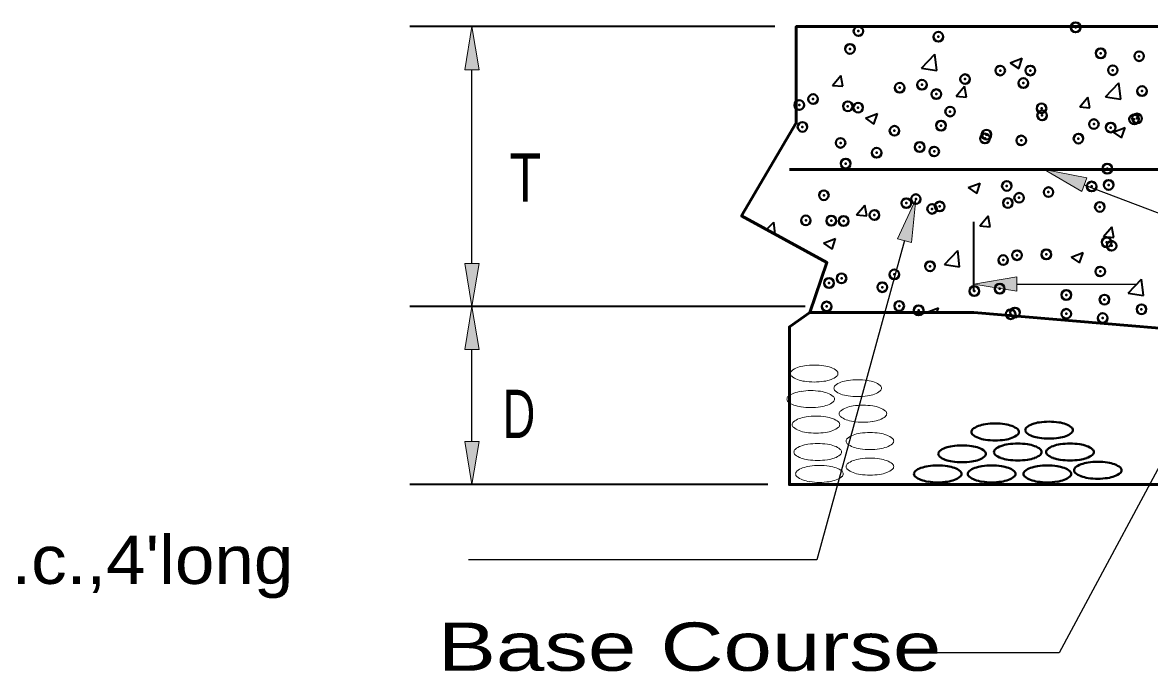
# Model space of a CAD drawing. Extents: x 36.4 to 71.7, y 0.5 to 22.5.
# Drawn here: x 41.345 to 44.615, y 8.235 to 10.118 of the extents above; entities that cross this region are included whole.
import ezdxf

# ---------------------------------------------------------------- set-up
doc = ezdxf.new("R2010")
doc.units = 0
doc.header["$LTSCALE"] = 0.056
doc.header["$PDMODE"] = 32
doc.header["$PDSIZE"] = 0.028
for name, color, linetype, lineweight in [('1', 7, 'Continuous', 40), ('3', 7, 'Continuous', 13), ('6', 7, 'Continuous', 13)]:
    doc.layers.add(name, color=color, linetype=linetype, lineweight=lineweight)

msp = doc.modelspace()

# ---------------------------------------------------------------- hatches: boundary and pattern name
at = {"layer": '1'}
for points in [[(42.67008, 9.98108), (42.62842, 9.98108), (42.64925, 10.10608), (42.64925, 10.10608)], [(42.67008, 9.41925), (42.62842, 9.41925), (42.64925, 9.29425), (42.64925, 9.29425)], [(44.23025, 9.3385), (44.23025, 9.38017), (44.10525, 9.35925), (44.10525, 9.35925)], [(42.67008, 9.16925), (42.62842, 9.16925), (42.64925, 9.29425), (42.64925, 9.29425)], [(42.67008, 8.9025), (42.62842, 8.9025), (42.64925, 8.7775), (42.64925, 8.7775)]]:
    msp.add_hatch(color=256, dxfattribs=at).paths.add_polyline_path(points)
at = {"layer": '3'}
for points in [[(44.41858, 9.62808), (44.43333, 9.667), (44.30908, 9.69192), (44.30908, 9.69192)], [(43.884, 9.49067), (43.92417, 9.47958), (43.93717, 9.60558), (43.93717, 9.60558)]]:
    msp.add_hatch(color=256, dxfattribs=at).paths.add_polyline_path(points)

# ---------------------------------------------------------------- linework, layer by layer
at = {"layer": '1', "lineweight": 35}
for p, q in [((43.52767, 10.10608), (42.46925, 10.10608)), ((43.95358, 9.98558), (43.9925, 10.02617)), ((43.99808, 9.97867), (43.99258, 10.02617)), ((44.21083, 10.0015), (44.24583, 10.015)), ((44.23567, 9.98475), (44.24583, 10.01492)), ((43.95358, 9.98558), (43.99808, 9.97867)), ((44.21083, 10.0015), (44.23567, 9.98475)), ((43.69533, 9.93575), (43.71942, 9.9645)), ((43.72525, 9.93317), (43.71942, 9.9645)), ((44.48725, 9.90283), (44.52617, 9.94342)), ((44.53167, 9.89592), (44.52617, 9.94342)), ((43.69533, 9.93575), (43.72517, 9.93317)), ((44.05392, 9.90442), (44.07808, 9.93308)), ((44.08383, 9.90175), (44.07808, 9.93308)), ((44.05392, 9.90442), (44.08383, 9.90175)), ((44.41258, 9.873), (44.43667, 9.90175)), ((44.4425, 9.87042), (44.43667, 9.90175)), ((44.48725, 9.90283), (44.53167, 9.89592)), ((43.79067, 9.84025), (43.82567, 9.85367)), ((43.81558, 9.8235), (43.82575, 9.85367)), ((44.41258, 9.873), (44.4425, 9.87042)), ((43.79067, 9.84025), (43.81558, 9.8235)), ((44.50925, 9.80025), (44.54425, 9.81367)), ((44.53417, 9.78342), (44.54425, 9.81367)), ((44.50925, 9.80025), (44.53417, 9.78342)), ((44.08917, 9.63892), (44.12417, 9.65242)), ((44.114, 9.62217), (44.12417, 9.65242)), ((44.08917, 9.63892), (44.114, 9.62217)), ((43.76467, 9.55967), (43.78883, 9.58842)), ((43.79458, 9.55708), (43.78883, 9.58842)), ((43.76467, 9.55967), (43.79458, 9.55708)), ((44.12333, 9.52825), (44.14742, 9.557)), ((44.15325, 9.52567), (44.14742, 9.557)), ((43.50425, 9.51725), (43.52525, 9.53917)), ((43.52933, 9.50358), (43.52525, 9.53908)), ((44.10525, 9.33875), (44.10525, 9.53933)), ((44.12333, 9.52825), (44.15325, 9.52567)), ((44.48192, 9.49692), (44.50608, 9.52567)), ((44.51183, 9.49425), (44.50608, 9.52567)), ((43.669, 9.47767), (43.70408, 9.49108)), ((43.69392, 9.46092), (43.70408, 9.49108)), ((44.48192, 9.49692), (44.51183, 9.49433)), ((43.669, 9.47767), (43.69392, 9.46092)), ((44.01992, 9.41575), (44.05883, 9.45633)), ((44.06433, 9.40892), (44.05883, 9.45633)), ((44.38758, 9.43767), (44.42258, 9.45108)), ((44.4125, 9.42083), (44.42258, 9.45108)), ((44.38758, 9.43767), (44.4125, 9.42083)), ((44.01992, 9.41575), (44.06433, 9.40892)), ((44.5535, 9.333), (44.59242, 9.37358)), ((44.598, 9.32608), (44.59242, 9.37358)), ((44.5535, 9.333), (44.598, 9.32608)), ((43.61583, 9.29425), (42.46925, 9.29425)), ((43.9675, 9.27633), (44.0025, 9.28983)), ((43.998, 9.27633), (44.0025, 9.28983)), ((43.9675, 9.27633), (43.96758, 9.27633)), ((43.50792, 8.7775), (42.46925, 8.7775))]:
    msp.add_line(p, q, dxfattribs=at)
at = {"layer": '1', "lineweight": 25}
for p, q in [((42.64925, 9.41925), (42.64925, 9.98108)), ((44.23025, 9.35933), (44.57725, 9.35933)), ((42.64925, 8.9025), (42.64925, 9.16925))]:
    msp.add_line(p, q, dxfattribs=at)
at = {"layer": '1', "lineweight": 53}
msp.add_line((47.36392, 9.69192), (43.57042, 9.69192), dxfattribs=at)
at = {"layer": '1', "lineweight": 13}
msp.add_line((43.61583, 9.29425), (42.46925, 9.29425), dxfattribs=at)
for points in [[(42.67008, 9.98108), (42.62842, 9.98108), (42.64925, 10.10608), (42.64925, 10.10608)], [(42.67008, 9.41925), (42.62842, 9.41925), (42.64925, 9.29425), (42.64925, 9.29425)], [(44.23025, 9.3385), (44.23025, 9.38017), (44.10525, 9.35925), (44.10525, 9.35925)], [(42.67008, 9.16925), (42.62842, 9.16925), (42.64925, 9.29425), (42.64925, 9.29425)], [(42.67008, 8.9025), (42.62842, 8.9025), (42.64925, 8.7775), (42.64925, 8.7775)]]:
    msp.add_lwpolyline(points, close=True, dxfattribs=at)
at = {"layer": '1', "lineweight": 53}
for points in [[(47.51525, 10.10608), (43.59017, 10.10608), (43.59017, 9.827), (43.43175, 9.55683), (43.67933, 9.42175), (43.62983, 9.27633), (44.10525, 9.27633), (46.07633, 9.11), (53.64175, 9.12625)], [(43.62983, 9.27633), (43.57042, 9.23475), (43.57042, 8.7775), (45.24308, 8.7775)]]:
    msp.add_lwpolyline(points, dxfattribs=at)
at = {"layer": '1', "lineweight": 13}
for centre, radius, start, end in [((43.64183, 8.93117), 0.193, 89.84207, 98.25709), ((43.64283, 8.93175), 0.19243, 81.73096, 90.14599), ((43.58358, 9.09958), 0.01025, 180.19847, 229.42992), ((43.5835, 9.0995), 0.01016, 130.3333, 179.56474), ((43.61117, 9.13175), 0.05258, 229.32889, 250.44364), ((43.61142, 9.06742), 0.05269, 109.77026, 130.885), ((43.63008, 9.01542), 0.10795, 98.52638, 109.76521), ((43.6545, 9.015), 0.10836, 70.28977, 81.5286), ((43.67325, 9.06742), 0.05269, 49.11499, 70.22974), ((43.6735, 9.13175), 0.05258, 289.55636, 310.6711), ((43.70117, 9.09958), 0.01012, 359.922, 49.15345), ((43.70108, 9.0995), 0.01021, 311.07972, 0.31117), ((43.63008, 9.18375), 0.10795, 250.23479, 261.47362), ((43.64233, 9.268), 0.19304, 261.57477, 269.98979), ((43.64225, 9.26742), 0.19248, 270.02264, 278.43766), ((43.6545, 9.18417), 0.10836, 278.47139, 289.71023), ((43.70967, 9.05725), 0.01012, 130.84655, 180.07799), ((43.73758, 9.02508), 0.05269, 109.77026, 130.885), ((43.75583, 8.97258), 0.10826, 98.25297, 109.4918), ((43.76858, 8.88933), 0.19248, 90.02264, 98.43766), ((43.7685, 8.88875), 0.19304, 81.57477, 89.98979), ((43.78125, 8.97258), 0.10826, 70.5082, 81.74703), ((43.7995, 9.02508), 0.05269, 49.11499, 70.22974), ((43.82742, 9.05725), 0.01012, 359.922, 49.15345), ((43.57342, 9.0255), 0.01021, 131.07972, 180.31117), ((43.57333, 9.02542), 0.01012, 179.922, 229.15345), ((43.601, 8.99325), 0.05258, 109.55636, 130.6711), ((43.62, 8.94083), 0.10836, 98.47139, 109.71022), ((43.63225, 8.857), 0.19304, 90.0102, 98.42523), ((43.63217, 8.85758), 0.19248, 81.56233, 89.97736), ((43.64442, 8.94083), 0.10836, 70.28977, 81.5286), ((43.66342, 8.99325), 0.05258, 49.32889, 70.44364), ((43.69108, 9.02542), 0.01012, 310.84655, 0.07799), ((43.691, 9.0255), 0.01021, 359.68883, 48.92027), ((43.70975, 9.05717), 0.01021, 179.68883, 228.92027), ((43.73733, 9.08942), 0.05258, 229.32889, 250.44364), ((43.75633, 9.14183), 0.10836, 250.28977, 261.5286), ((43.76858, 9.22508), 0.19248, 261.56233, 269.97736), ((43.7685, 9.22567), 0.19304, 270.0102, 278.42523), ((43.78075, 9.14183), 0.10836, 278.47139, 289.71023), ((43.79975, 9.08942), 0.05258, 289.55636, 310.6711), ((43.82733, 9.05717), 0.01021, 311.07972, 0.31117), ((43.60125, 9.05758), 0.05269, 229.11499, 250.22974), ((43.6195, 9.11008), 0.10826, 250.5082, 261.74703), ((43.63225, 9.19392), 0.19304, 261.57477, 269.98979), ((43.63217, 9.19333), 0.19248, 270.02264, 278.43766), ((43.64492, 9.11008), 0.10826, 278.25297, 289.4918), ((43.66317, 9.05758), 0.05269, 289.77026, 310.885), ((43.7525, 8.95092), 0.05258, 109.55636, 130.6711), ((43.7715, 8.8985), 0.10836, 98.47139, 109.71022), ((43.78375, 8.81525), 0.19248, 90.02264, 98.43766), ((43.78367, 8.81467), 0.19304, 81.57477, 89.98979), ((43.79592, 8.89892), 0.10795, 70.23479, 81.47362), ((43.81483, 8.95092), 0.05258, 49.32889, 70.44364), ((43.61642, 8.91917), 0.05269, 109.77026, 130.885), ((43.63517, 8.86675), 0.10836, 98.47139, 109.71022), ((43.64683, 8.7835), 0.19243, 89.85401, 98.26903), ((43.64783, 8.78292), 0.193, 81.7429, 90.15793), ((43.65958, 8.86675), 0.10836, 70.28977, 81.5286), ((43.67833, 8.91917), 0.05269, 49.11499, 70.22974), ((43.72492, 8.98308), 0.01025, 130.57008, 179.80152), ((43.72483, 8.98317), 0.01016, 180.43525, 229.6667), ((43.75275, 9.01525), 0.05269, 229.11499, 250.22974), ((43.7715, 9.06767), 0.10836, 250.28977, 261.5286), ((43.78317, 9.15092), 0.19243, 261.73096, 270.14599), ((43.78417, 9.1515), 0.193, 269.84207, 278.25709), ((43.79592, 9.06725), 0.10795, 278.52638, 289.76521), ((43.81458, 9.01525), 0.05269, 289.77026, 310.885), ((43.8425, 8.98317), 0.01016, 310.3333, 359.56474), ((43.84242, 8.98308), 0.01025, 0.19847, 49.42992), ((43.58858, 8.95125), 0.01021, 179.68883, 228.92027), ((43.5885, 8.95133), 0.01012, 130.84655, 180.07799), ((43.61617, 8.9835), 0.05258, 229.32889, 250.44364), ((43.63517, 9.03592), 0.10836, 250.28977, 261.5286), ((43.64742, 9.11917), 0.19248, 261.56233, 269.97736), ((43.64733, 9.11975), 0.19304, 270.0102, 278.42523), ((43.65958, 9.03592), 0.10836, 278.47139, 289.71023), ((43.67858, 8.9835), 0.05258, 289.55636, 310.6711), ((43.70625, 8.95133), 0.01012, 359.922, 49.15345), ((43.70617, 8.95125), 0.01021, 311.07972, 0.31117), ((43.80392, 8.73583), 0.19248, 90.02264, 98.43766), ((43.80383, 8.73525), 0.19304, 81.57477, 89.98979), ((43.63975, 8.78725), 0.10826, 98.25297, 109.4918), ((43.6525, 8.704), 0.19248, 90.02264, 98.43766), ((43.65233, 8.704), 0.19248, 81.56233, 89.97736), ((43.66508, 8.78725), 0.10826, 70.5082, 81.74703), ((43.74508, 8.90375), 0.01021, 131.07972, 180.31117), ((43.74508, 8.90358), 0.01021, 179.68883, 228.92027), ((43.77267, 8.8715), 0.05258, 109.55636, 130.6711), ((43.77267, 8.93583), 0.05258, 229.32889, 250.44364), ((43.79167, 8.81908), 0.10836, 98.47139, 109.71022), ((43.81608, 8.81908), 0.10836, 70.28977, 81.5286), ((43.83508, 8.8715), 0.05258, 49.32889, 70.44364), ((43.83508, 8.93583), 0.05258, 289.55636, 310.6711), ((43.86267, 8.90375), 0.01021, 359.68883, 48.92027), ((43.86267, 8.90358), 0.01021, 311.07972, 0.31117), ((43.59358, 8.87183), 0.01016, 130.3333, 179.56474), ((43.59367, 8.87192), 0.01025, 180.19847, 229.42992), ((43.62125, 8.90408), 0.05258, 229.32889, 250.44364), ((43.6215, 8.83975), 0.05269, 109.77026, 130.885), ((43.68333, 8.83975), 0.05269, 49.11499, 70.22974), ((43.68358, 8.90408), 0.05258, 289.55636, 310.6711), ((43.71125, 8.87183), 0.01016, 0.43525, 49.6667), ((43.71117, 8.87192), 0.01025, 310.57008, 359.80152), ((43.79167, 8.98825), 0.10836, 250.28977, 261.5286), ((43.80392, 9.0715), 0.19248, 261.56233, 269.97736), ((43.80383, 9.07208), 0.19304, 270.0102, 278.42523), ((43.81608, 8.98825), 0.10836, 278.47139, 289.71023), ((43.64025, 8.9565), 0.10836, 250.28977, 261.5286), ((43.64525, 8.72375), 0.10836, 98.47139, 109.71022), ((43.6525, 9.03975), 0.19248, 261.56233, 269.97736), ((43.6575, 8.63992), 0.19304, 90.0102, 98.42523), ((43.65233, 9.03975), 0.19248, 270.02264, 278.43766), ((43.65742, 8.6405), 0.19248, 81.56233, 89.97736), ((43.66458, 8.9565), 0.10836, 278.47139, 289.71023), ((43.66967, 8.72375), 0.10836, 70.28977, 81.5286), ((43.74508, 8.82958), 0.01021, 131.07972, 180.31117), ((43.745, 8.8295), 0.01012, 179.922, 229.15345), ((43.77267, 8.79733), 0.05258, 109.55636, 130.6711), ((43.79167, 8.74492), 0.10836, 98.47139, 109.71022), ((43.80392, 8.66167), 0.19248, 90.02264, 98.43766), ((43.80383, 8.66108), 0.19304, 81.57477, 89.98979), ((43.81608, 8.74492), 0.10836, 70.28977, 81.5286), ((43.83508, 8.79733), 0.05258, 49.32889, 70.44364), ((43.86275, 8.8295), 0.01012, 310.84655, 0.07799), ((43.86267, 8.82958), 0.01021, 359.68883, 48.92027), ((43.59867, 8.80842), 0.01021, 131.07972, 180.31117), ((43.59858, 8.80833), 0.01012, 179.922, 229.15345), ((43.62625, 8.77617), 0.05258, 109.55636, 130.6711), ((43.6265, 8.8405), 0.05269, 229.11499, 250.22974), ((43.68842, 8.8405), 0.05269, 289.77026, 310.885), ((43.68867, 8.77617), 0.05258, 49.32889, 70.44364), ((43.71633, 8.80833), 0.01012, 310.84655, 0.07799), ((43.71625, 8.80842), 0.01021, 359.68883, 48.92027), ((43.77292, 8.86167), 0.05269, 229.11499, 250.22974), ((43.79117, 8.91417), 0.10826, 250.5082, 261.74703), ((43.80392, 8.99742), 0.19248, 261.56233, 269.97736), ((43.80383, 8.998), 0.19304, 270.0102, 278.42523), ((43.81658, 8.91417), 0.10826, 278.25297, 289.4918), ((43.83483, 8.86167), 0.05269, 289.77026, 310.885), ((43.64475, 8.893), 0.10826, 250.5082, 261.74703), ((43.6575, 8.97683), 0.19304, 261.57477, 269.98979), ((43.65742, 8.97625), 0.19248, 270.02264, 278.43766), ((43.67017, 8.893), 0.10826, 278.25297, 289.4918)]:
    msp.add_arc(centre, radius, start, end, dxfattribs=at)
at = {"layer": '1'}
for centre, radius, start, end in [((44.32392, 8.76758), 0.19248, 90.02264, 98.43766), ((44.32383, 8.767), 0.19304, 81.57477, 89.98979), ((44.10858, 8.93008), 0.01021, 179.68883, 228.92027), ((44.1085, 8.93017), 0.01012, 130.84655, 180.07799), ((44.13642, 8.898), 0.05269, 109.77026, 130.885), ((44.15467, 8.8455), 0.10826, 98.25297, 109.4918), ((44.16742, 8.76225), 0.19248, 90.02264, 98.43766), ((44.16733, 8.76167), 0.19304, 81.57477, 89.98979), ((44.18, 8.84592), 0.10785, 70.454, 81.69283), ((44.19825, 8.898), 0.05269, 49.11499, 70.22974), ((44.22617, 8.93008), 0.01016, 0.43525, 49.6667), ((44.22608, 8.93017), 0.01025, 310.57008, 359.80152), ((44.26508, 8.93542), 0.01025, 130.57008, 179.80152), ((44.265, 8.9355), 0.01016, 180.43525, 229.6667), ((44.29267, 8.90325), 0.05258, 109.55636, 130.6711), ((44.29292, 8.96758), 0.05269, 229.11499, 250.22974), ((44.31167, 8.85083), 0.10836, 98.47139, 109.71022), ((44.33608, 8.85125), 0.10795, 70.23479, 81.47362), ((44.35475, 8.96758), 0.05269, 289.77026, 310.885), ((44.355, 8.90325), 0.05258, 49.32889, 70.44364), ((44.38258, 8.93542), 0.01025, 0.19847, 49.42992), ((44.38267, 8.9355), 0.01016, 310.3333, 359.56474), ((44.13617, 8.96233), 0.05258, 229.32889, 250.44364), ((44.15517, 9.01475), 0.10836, 250.28977, 261.5286), ((44.16742, 9.098), 0.19248, 261.56233, 269.97736), ((44.16733, 9.09858), 0.19304, 270.0102, 278.42523), ((44.22025, 8.78725), 0.10826, 98.25297, 109.4918), ((44.17958, 9.01433), 0.10795, 278.52638, 289.76521), ((44.233, 8.70342), 0.19304, 90.0102, 98.42523), ((44.1985, 8.96233), 0.05258, 289.55636, 310.6711), ((44.23292, 8.704), 0.19248, 81.56233, 89.97736), ((44.24567, 8.78725), 0.10826, 70.5082, 81.74703), ((44.31117, 9.02008), 0.10826, 250.5082, 261.74703), ((44.32392, 9.10333), 0.19248, 261.56233, 269.97736), ((44.32383, 9.10392), 0.19304, 270.0102, 278.42523), ((44.37175, 8.78725), 0.10826, 98.25297, 109.4918), ((44.3365, 9.01967), 0.10785, 278.30717, 289.546), ((44.3845, 8.704), 0.19248, 90.02264, 98.43766), ((44.38442, 8.70342), 0.19304, 81.57477, 89.98979), ((44.39708, 8.78767), 0.10785, 70.454, 81.69283), ((44.01267, 8.86658), 0.01025, 130.57008, 179.80152), ((44.01258, 8.86667), 0.01016, 180.43525, 229.6667), ((44.04025, 8.83442), 0.05258, 109.55636, 130.6711), ((44.05925, 8.782), 0.10836, 98.47139, 109.71022), ((44.0715, 8.69875), 0.19248, 90.02264, 98.43766), ((44.07142, 8.69817), 0.19304, 81.57477, 89.98979), ((44.08367, 8.78242), 0.10795, 70.23479, 81.47362), ((44.10258, 8.83442), 0.05258, 49.32889, 70.44364), ((44.13025, 8.86667), 0.01016, 310.3333, 359.56474), ((44.13017, 8.86658), 0.01025, 0.19847, 49.42992), ((44.17408, 8.87192), 0.01012, 130.84655, 180.07799), ((44.17417, 8.87183), 0.01021, 179.68883, 228.92027), ((44.20175, 8.90408), 0.05258, 229.32889, 250.44364), ((44.202, 8.83975), 0.05269, 109.77026, 130.885), ((44.26392, 8.83975), 0.05269, 49.11499, 70.22974), ((44.26417, 8.90408), 0.05258, 289.55636, 310.6711), ((44.29183, 8.87192), 0.01012, 359.922, 49.15345), ((44.29175, 8.87183), 0.01021, 311.07972, 0.31117), ((44.32558, 8.87183), 0.01016, 130.3333, 179.56474), ((44.32567, 8.87192), 0.01025, 180.19847, 229.42992), ((44.35325, 8.90408), 0.05258, 229.32889, 250.44364), ((44.3535, 8.83975), 0.05269, 109.77026, 130.885), ((44.41533, 8.83975), 0.05269, 49.11499, 70.22974), ((44.41558, 8.90408), 0.05258, 289.55636, 310.6711), ((44.44325, 8.87183), 0.01016, 0.43525, 49.6667), ((44.44317, 8.87192), 0.01025, 310.57008, 359.80152), ((43.9885, 8.72417), 0.10795, 98.52638, 109.76521), ((44.00075, 8.63992), 0.19304, 90.0102, 98.42523), ((44.00067, 8.6405), 0.19248, 81.56233, 89.97736), ((44.0405, 8.89875), 0.05269, 229.11499, 250.22974), ((44.05875, 8.95125), 0.10826, 250.5082, 261.74703), ((44.01292, 8.72375), 0.10836, 70.28977, 81.5286), ((44.0715, 9.0345), 0.19248, 261.56233, 269.97736), ((44.07142, 9.03508), 0.19304, 270.0102, 278.42523), ((44.08408, 8.95083), 0.10785, 278.30717, 289.546), ((44.145, 8.72417), 0.10795, 98.52638, 109.76521), ((44.10233, 8.89875), 0.05269, 289.77026, 310.885), ((44.15725, 8.63992), 0.19304, 90.0102, 98.42523), ((44.15717, 8.6405), 0.19248, 81.56233, 89.97736), ((44.22075, 8.9565), 0.10836, 250.28977, 261.5286), ((44.16942, 8.72375), 0.10836, 70.28977, 81.5286), ((44.233, 9.04033), 0.19304, 261.57477, 269.98979), ((44.23292, 9.03975), 0.19248, 270.02264, 278.43766), ((44.24517, 8.9565), 0.10836, 278.47139, 289.71023), ((44.30658, 8.72375), 0.10836, 98.47139, 109.71022), ((44.31883, 8.6405), 0.19248, 90.02264, 98.43766), ((44.31875, 8.63992), 0.19304, 81.57477, 89.98979), ((44.37225, 8.9565), 0.10836, 250.28977, 261.5286), ((44.331, 8.72375), 0.10836, 70.28977, 81.5286), ((44.3845, 9.03975), 0.19248, 261.56233, 269.97736), ((44.38442, 9.04033), 0.19304, 270.0102, 278.42523), ((44.434, 8.78675), 0.05258, 109.55636, 130.6711), ((44.39667, 8.95608), 0.10795, 278.52638, 289.76521), ((44.453, 8.73433), 0.10836, 98.47139, 109.71022), ((44.46525, 8.65108), 0.19248, 90.02264, 98.43766), ((44.46517, 8.6505), 0.19304, 81.57477, 89.98979), ((44.47742, 8.73475), 0.10795, 70.23479, 81.47362), ((44.49633, 8.78675), 0.05258, 49.32889, 70.44364), ((43.942, 8.80833), 0.01025, 130.57008, 179.80152), ((43.94192, 8.80842), 0.01016, 180.43525, 229.6667), ((43.96958, 8.77617), 0.05258, 109.55636, 130.6711), ((43.96983, 8.8405), 0.05269, 229.11499, 250.22974), ((44.03167, 8.8405), 0.05269, 289.77026, 310.885), ((44.03192, 8.77617), 0.05258, 49.32889, 70.44364), ((44.05958, 8.80842), 0.01016, 310.3333, 359.56474), ((44.0595, 8.80833), 0.01025, 0.19847, 49.42992), ((44.0985, 8.80833), 0.01025, 130.57008, 179.80152), ((44.09842, 8.80842), 0.01016, 180.43525, 229.6667), ((44.12608, 8.77617), 0.05258, 109.55636, 130.6711), ((44.12633, 8.8405), 0.05269, 229.11499, 250.22974), ((44.18817, 8.8405), 0.05269, 289.77026, 310.885), ((44.18842, 8.77617), 0.05258, 49.32889, 70.44364), ((44.21608, 8.80842), 0.01016, 310.3333, 359.56474), ((44.216, 8.80833), 0.01025, 0.19847, 49.42992), ((44.26, 8.80842), 0.01021, 131.07972, 180.31117), ((44.25992, 8.80833), 0.01012, 179.922, 229.15345), ((44.28758, 8.77617), 0.05258, 109.55636, 130.6711), ((44.28783, 8.8405), 0.05269, 229.11499, 250.22974), ((44.34975, 8.8405), 0.05269, 289.77026, 310.885), ((44.35, 8.77617), 0.05258, 49.32889, 70.44364), ((44.37758, 8.80842), 0.01021, 359.68883, 48.92027), ((44.37767, 8.80833), 0.01012, 310.84655, 0.07799), ((44.40642, 8.819), 0.01021, 131.07972, 180.31117), ((44.40633, 8.81892), 0.01012, 179.922, 229.15345), ((44.43425, 8.85108), 0.05269, 229.11499, 250.22974), ((44.4525, 8.90358), 0.10826, 250.5082, 261.74703), ((44.46525, 8.98683), 0.19248, 261.56233, 269.97736), ((44.46517, 8.98742), 0.19304, 270.0102, 278.42523), ((44.47783, 8.90317), 0.10785, 278.30717, 289.546), ((44.49608, 8.85108), 0.05269, 289.77026, 310.885), ((44.524, 8.819), 0.01016, 310.3333, 359.56474), ((44.52392, 8.81892), 0.01025, 0.19847, 49.42992), ((43.98808, 8.89258), 0.10785, 250.454, 261.69283), ((44.00075, 8.97683), 0.19304, 261.57477, 269.98979), ((44.00067, 8.97625), 0.19248, 270.02264, 278.43766), ((44.01342, 8.893), 0.10826, 278.25297, 289.4918), ((44.14458, 8.89258), 0.10785, 250.454, 261.69283), ((44.15725, 8.97683), 0.19304, 261.57477, 269.98979), ((44.15717, 8.97625), 0.19248, 270.02264, 278.43766), ((44.16992, 8.893), 0.10826, 278.25297, 289.4918), ((44.30608, 8.893), 0.10826, 250.5082, 261.74703), ((44.31883, 8.97625), 0.19248, 261.56233, 269.97736), ((44.31875, 8.97683), 0.19304, 270.0102, 278.42523), ((44.3315, 8.893), 0.10826, 278.25297, 289.4918)]:
    msp.add_arc(centre, radius, start, end, dxfattribs=at)
for p in [(43.77067, 10.093), (44.40092, 10.104), (44.00258, 10.07675), (43.74592, 10.0415), (44.47358, 10.02883), (44.58517, 10.02033), (44.182, 9.97875), (44.26942, 9.97875), (44.50875, 9.97975), (43.89042, 9.92875), (43.95483, 9.93742), (44.08008, 9.95383), (44.24908, 9.94225), (43.63908, 9.89583), (43.9965, 9.91025), (44.59342, 9.91908), (43.59883, 9.87867), (43.73983, 9.87508), (43.76975, 9.87108), (44.30183, 9.869), (44.03667, 9.85983), (44.30358, 9.8485), (44.5705, 9.83725), (44.57883, 9.83967), (43.60825, 9.81517), (43.87517, 9.80392), (44.01025, 9.81892), (44.45367, 9.82317), (44.50267, 9.81333), (43.71867, 9.76892), (44.13783, 9.78158), (44.14208, 9.79267), (44.243, 9.77583), (44.409, 9.78133), (43.82333, 9.74017), (43.9485, 9.75667), (43.9905, 9.74383), (43.73375, 9.70867), (44.49275, 9.694), (44.20117, 9.644), (44.44725, 9.64242), (44.49667, 9.64692), (43.67025, 9.61692), (43.93717, 9.60567), (44.23692, 9.60942), (44.32208, 9.62592), (43.90958, 9.59392), (43.98442, 9.57742), (44.00633, 9.58433), (44.20408, 9.59442), (44.471, 9.58308), (43.618, 9.54383), (43.69183, 9.543), (43.72767, 9.54217), (43.817, 9.55942), (44.49058, 9.48042), (44.50508, 9.47017), (44.23083, 9.44292), (44.31575, 9.44525), (43.97833, 9.41092), (44.19058, 9.42875), (43.72158, 9.37575), (43.87483, 9.38717), (44.47217, 9.39567), (43.68542, 9.36225), (43.83983, 9.35017), (44.10675, 9.33892), (44.18058, 9.34567), (44.37367, 9.32758), (44.4845, 9.314), (43.67833, 9.29425), (43.88892, 9.29558), (43.94525, 9.283), (44.22475, 9.2765), (44.37358, 9.27292), (44.59192, 9.28592), (44.21217, 9.27175), (44.47908, 9.26042)]:
    msp.add_point(p, dxfattribs=at)
at = {"layer": '3'}
for points in [[(44.41858, 9.62808), (44.43333, 9.667), (44.30908, 9.69192), (44.30908, 9.69192)], [(43.884, 9.49067), (43.92417, 9.47958), (43.93717, 9.60558), (43.93717, 9.60558)]]:
    msp.add_lwpolyline(points, close=True, dxfattribs=at)
at = {"layer": '3', "lineweight": 25}
for points in [[(44.426, 9.64758), (44.84925, 9.48683), (45.48417, 9.48683)], [(43.90408, 9.48517), (43.64958, 8.55933), (42.63933, 8.55933)], [(44.7295, 8.98958), (44.35283, 8.28917), (43.99625, 8.28917)]]:
    msp.add_lwpolyline(points, dxfattribs=at)
at = {"layer": '6'}
for p, q in [((42.64925, 10.10608), (42.64933, 10.10608)), ((43.59017, 10.10608), (43.59025, 10.10608)), ((44.10525, 9.35933), (44.10533, 9.35933)), ((42.64925, 9.29425), (42.64933, 9.29425)), ((43.67833, 9.29425), (43.67842, 9.29425)), ((43.67833, 9.29425), (43.67842, 9.29425)), ((44.10525, 9.27625), (44.10533, 9.27625)), ((43.57042, 8.7775), (43.5705, 8.7775))]:
    msp.add_line(p, q, dxfattribs=at)

# ---------------------------------------------------------------- texts
at = {"layer": '3'}
for s, width, p in [('T', 0.8, (42.75817, 9.59842)), ('D', 0.7, (42.73833, 8.91258)), ('#5 Bars,12"c.c.,4\'long', 1.1, (40.141, 8.48925)), ('Base Course', 1.35, (42.55017, 8.23717))]:
    msp.add_text(s, height=0.14, dxfattribs=dict(at, width=width)).set_placement(p)

doc.saveas('drawing.dxf')
